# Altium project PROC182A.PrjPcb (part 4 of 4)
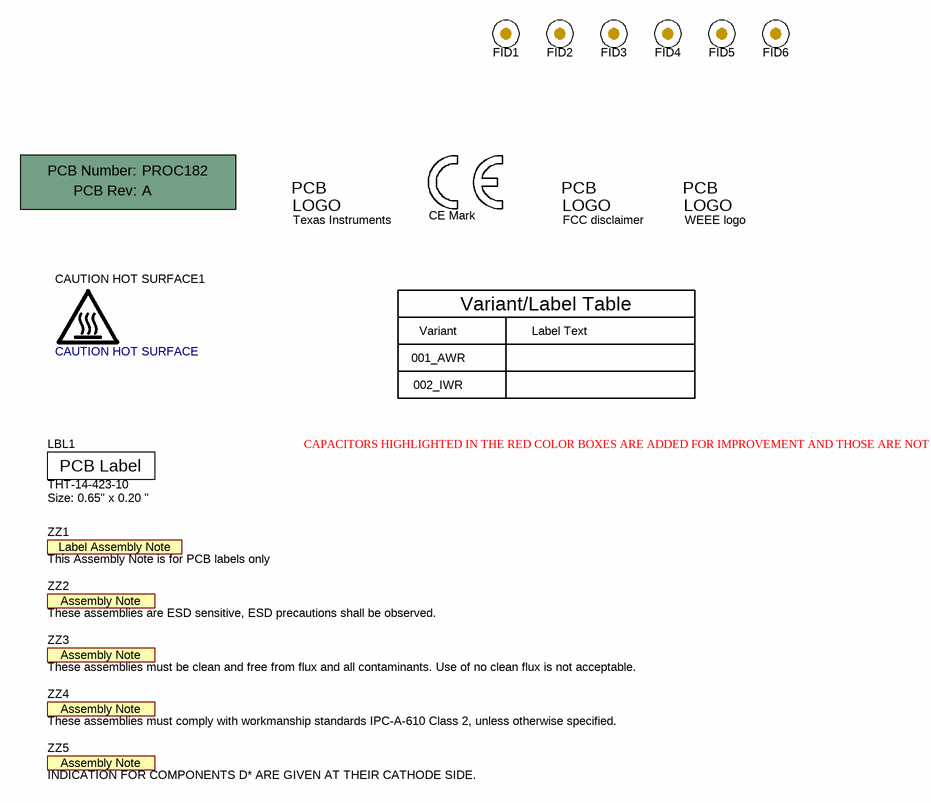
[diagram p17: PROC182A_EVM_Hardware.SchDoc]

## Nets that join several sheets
5V_IN_USB: PROC182A_USB_PWR_DC_Jack_Switch (15 pins), PROC182A_PMIC (C42.2 U13.6)
FTDI_VBUS: PROC182A_USB_PWR_DC_Jack_Switch (L8.1), PROC182A_FTDI (C157.2 J10.1 R259.2)
GND: PROC182A_USB_PWR_DC_Jack_Switch (45 pins), PROC182A_PMIC (46 pins), PROC182A_Chip (110 pins), PROC182A_Decoupling_caps- QSPI Flash (33 pins), PROC182A_Temp_Current_sensors_EPROM (24 pins), PROC182A_Analog_Mux_SOP_Ctrl (19 pins), PROC182A_Analog_MUX_SPI (9 pins), PROC182A_XDS110_Interface (33 pins), PROC182A_MUX_CAN_FD (8 pins), PROC182A_CAN_LIN_PHY_Interface (10 pins), PROC182A_FTDI (42 pins), PROC182A_DCA1000_Connector_Reset (25 pins), PROC182A_I2C_SPI_Connector (9 pins)
RADAR_1P2_RF: PROC182A_Chip (U1.D8 U1.D9 U1.D10), PROC182A_Decoupling_caps- QSPI Flash (C24.2 C44.1), PROC182A_Temp_Current_sensors_EPROM (R134.2 U25.9)
RADAR_1V2: PROC182A_Chip (25 pins), PROC182A_Decoupling_caps- QSPI Flash (8 pins), PROC182A_Temp_Current_sensors_EPROM (R193.2 U8.9)
RADAR_1V4_APLL: PROC182A_Chip (U1.H7), PROC182A_Decoupling_caps- QSPI Flash (C22.2)
RADAR_1V4_SYNTH: PROC182A_Chip (U1.F3), PROC182A_Decoupling_caps- QSPI Flash (C18.2)
RADAR_1V8: PROC182A_Chip (9 pins), PROC182A_Decoupling_caps- QSPI Flash (11 pins), PROC182A_Temp_Current_sensors_EPROM (R192.2 U6.9)
RADAR_1V_RF_OUT: PROC182A_Chip (5 pins), PROC182A_Decoupling_caps- QSPI Flash (C9.2 C19.2)
RADAR_3V3: PROC182A_Chip (10 pins), PROC182A_Decoupling_caps- QSPI Flash (C16.2 C17.2 C21.2), PROC182A_Temp_Current_sensors_EPROM (R200.2 U7.9)
RADAR_VBGAP: PROC182A_Chip (U1.K3), PROC182A_Decoupling_caps- QSPI Flash (C6.1)
REG_1V2: PROC182A_PMIC (C20.2 C91.2 FB2.2), PROC182A_Temp_Current_sensors_EPROM (R193.1 U8.8 U8.10)
REG_1V8: PROC182A_PMIC (C3.2 C82.2 FB1.2), PROC182A_Temp_Current_sensors_EPROM (R192.1 U6.8 U6.10)
REG_RF_1V2: PROC182A_PMIC (C27.2 C103.2 FB3.2), PROC182A_Temp_Current_sensors_EPROM (R134.1 U25.8 U25.10)
VCC_3V3: PROC182A_USB_PWR_DC_Jack_Switch (R172.2), PROC182A_PMIC (5 pins), PROC182A_Decoupling_caps- QSPI Flash (6 pins), PROC182A_Temp_Current_sensors_EPROM (33 pins), PROC182A_Analog_Mux_SOP_Ctrl (14 pins), PROC182A_Analog_MUX_SPI (11 pins), PROC182A_MUX_CAN_FD (8 pins), PROC182A_CAN_LIN_PHY_Interface (C38.2 R17.2 R22.2 U5.5), PROC182A_FTDI (R99.2), PROC182A_DCA1000_Connector_Reset (13 pins), PROC182A_I2C_SPI_Connector (8 pins)
VCC_CAN_3V3: PROC182A_PMIC (C72.2 L4.2), PROC182A_MUX_CAN_FD (R129.2), PROC182A_CAN_LIN_PHY_Interface (R69.2)
VCC_XDS_3V3: PROC182A_PMIC (C105.1 TP20.1 U13.1), PROC182A_XDS110_Interface (26 pins), PROC182A_FTDI (L7.1)
VPP_1P7: PROC182A_PMIC (P1.1), PROC182A_Chip (C31.1 U1.R4)
VSYS_IN: PROC182A_USB_PWR_DC_Jack_Switch (8 pins), PROC182A_PMIC (5 pins), PROC182A_CAN_LIN_PHY_Interface (J4.1 R31.1), PROC182A_DCA1000_Connector_Reset (R30.1), PROC182A_I2C_SPI_Connector (R155.2)
XDSET_1_VBUS: PROC182A_USB_PWR_DC_Jack_Switch (R1.1 U9.6), PROC182A_XDS110_Interface (R169.2 R236.2)
CAN_FD_B_PHY_RX: PROC182A_Chip (U1.U12), PROC182A_MUX_CAN_FD (R143.1)
CAN_FD_B_PHY_TX: PROC182A_Chip (U1.R11), PROC182A_MUX_CAN_FD (R132.1)
CAN_FD_B_STB_CTRL: PROC182A_Analog_Mux_SOP_Ctrl (S1.1), PROC182A_MUX_CAN_FD (R133.1)
CAN_FD_RX: PROC182A_MUX_CAN_FD (U18.5), PROC182A_CAN_LIN_PHY_Interface (R80.1)
CAN_FD_TX: PROC182A_MUX_CAN_FD (U18.9), PROC182A_CAN_LIN_PHY_Interface (R78.1)
CAN_FD_UARTA_RX: PROC182A_Chip (U1.R10), PROC182A_MUX_CAN_FD (U18.6)
CAN_FD_UARTA_TX: PROC182A_Chip (U1.T10), PROC182A_MUX_CAN_FD (U18.10)
CAN_STB_CTRL: PROC182A_Analog_Mux_SOP_Ctrl (S4.1), PROC182A_CAN_LIN_PHY_Interface (R3.1)
DCA_LP_FTDI_HOST_INTR_1: PROC182A_Chip (R81.2 R261.2 R276.1), PROC182A_Analog_MUX_SPI (U28.10)
DCA_LP_FTDI_SPIA_CLK: PROC182A_Chip (U1.A16), PROC182A_Analog_MUX_SPI (U28.4)
DCA_LP_FTDI_SPIA_CS: PROC182A_Chip (R246.1 U1.B17), PROC182A_Analog_MUX_SPI (U28.6)
DCA_LP_FTDI_SPIA_MISO: PROC182A_Chip (R284.1), PROC182A_Analog_MUX_SPI (U28.7)
DCA_LP_FTDI_SPIA_MOSI: PROC182A_Chip (U1.A15), PROC182A_Analog_MUX_SPI (U28.9)
DCA_LP_HOST_INTR_1: PROC182A_Analog_MUX_SPI (U28.19), PROC182A_DCA1000_Connector_Reset (R42.2), PROC182A_I2C_SPI_Connector (J2.2 R223.2)
DCA_LP_RS232_RX: PROC182A_Analog_Mux_SOP_Ctrl (U12.3), PROC182A_DCA1000_Connector_Reset (R61.1), PROC182A_I2C_SPI_Connector (R163.1 R178.1)
DCA_LP_RS232_TX: PROC182A_Analog_Mux_SOP_Ctrl (U12.15), PROC182A_DCA1000_Connector_Reset (R62.1), PROC182A_I2C_SPI_Connector (R156.1 R176.1)
DCA_LP_SPIA_CLK: PROC182A_Analog_MUX_SPI (U28.2), PROC182A_DCA1000_Connector_Reset (R41.1), PROC182A_I2C_SPI_Connector (J2.3 R210.1)
DCA_LP_SPIA_CS: PROC182A_Analog_MUX_SPI (U28.1), PROC182A_DCA1000_Connector_Reset (R39.1), PROC182A_I2C_SPI_Connector (J2.4 R173.1 R177.2)
DCA_LP_SPIA_MISO: PROC182A_Analog_MUX_SPI (U28.23), PROC182A_DCA1000_Connector_Reset (R53.2), PROC182A_I2C_SPI_Connector (J2.5 R221.2)
DCA_LP_SPIA_MOSI: PROC182A_Analog_MUX_SPI (U28.21), PROC182A_DCA1000_Connector_Reset (R52.1), PROC182A_I2C_SPI_Connector (J2.6 R201.2)
DCA_LP_UARTA_RX: PROC182A_Analog_Mux_SOP_Ctrl (U16.3), PROC182A_DCA1000_Connector_Reset (R152.2), PROC182A_I2C_SPI_Connector (J9.2 R198.1 R212.1)
DCA_LP_UARTA_TX: PROC182A_Analog_Mux_SOP_Ctrl (U16.1), PROC182A_DCA1000_Connector_Reset (R153.2), PROC182A_I2C_SPI_Connector (J9.1 R180.1 R182.1)
DCA_TCK: PROC182A_Analog_Mux_SOP_Ctrl (U4.16), PROC182A_DCA1000_Connector_Reset (R38.2)
DCA_TDI: PROC182A_Analog_Mux_SOP_Ctrl (U4.3), PROC182A_DCA1000_Connector_Reset (R37.1)
DCA_TDO: PROC182A_Analog_Mux_SOP_Ctrl (U4.9), PROC182A_DCA1000_Connector_Reset (R34.2)
DCA_TMS: PROC182A_Analog_Mux_SOP_Ctrl (U4.12), PROC182A_DCA1000_Connector_Reset (R40.2)
FTDI_DCA_LP_RS232_RX: PROC182A_Analog_Mux_SOP_Ctrl (U12.2), PROC182A_MUX_CAN_FD (U18.3)
FTDI_DCA_LP_RS232_TX: PROC182A_Analog_Mux_SOP_Ctrl (U12.14), PROC182A_MUX_CAN_FD (U18.15)
FTDI_HOST_INTR_1: PROC182A_Analog_MUX_SPI (U28.18), PROC182A_FTDI (R216.2 R217.2)
FTDI_RS232_RX: PROC182A_Analog_Mux_SOP_Ctrl (U12.1), PROC182A_FTDI (R120.2)
FTDI_RS232_TX: PROC182A_Analog_Mux_SOP_Ctrl (U12.13), PROC182A_FTDI (R121.2)
FTDI_SOP0: PROC182A_Analog_Mux_SOP_Ctrl (R13.1 R43.2 R235.1), PROC182A_FTDI (R249.2)
FTDI_SOP1: PROC182A_Analog_Mux_SOP_Ctrl (R16.1 R67.2 R244.1), PROC182A_FTDI (R248.2)
FTDI_SPI_CLK: PROC182A_Analog_MUX_SPI (U28.11), PROC182A_FTDI (R186.2)
FTDI_SPI_CS: PROC182A_Analog_MUX_SPI (U28.13), PROC182A_FTDI (R99.1 R209.2)
FTDI_SPI_MISO: PROC182A_Analog_MUX_SPI (U28.15), PROC182A_FTDI (R189.2)
FTDI_SPI_MOSI: PROC182A_Analog_MUX_SPI (U28.17), PROC182A_FTDI (R187.2)
FTDI_UARTA_RX: PROC182A_Analog_Mux_SOP_Ctrl (U16.4), PROC182A_FTDI (R118.2)
FTDI_UARTA_TX: PROC182A_Analog_Mux_SOP_Ctrl (U16.2), PROC182A_FTDI (R119.2)
HARDWARE_TRIGGER: PROC182A_Chip (J15.2), PROC182A_I2C_SPI_Connector (R254.1)
HOST_CLK_REQ_SPIB_MISO: PROC182A_Chip (R270.2), PROC182A_Analog_MUX_SPI (U30.7)
I2C_SCL: PROC182A_PMIC (R89.1), PROC182A_Temp_Current_sensors_EPROM (7 pins), PROC182A_Analog_MUX_SPI (U30.16), PROC182A_XDS110_Interface (R199.1 S5.2), PROC182A_FTDI (R96.2), PROC182A_DCA1000_Connector_Reset (R60.1), PROC182A_I2C_SPI_Connector (J1.1 R164.1 R224.1)
I2C_SCL_SPIB_CLK: PROC182A_Chip (U1.N16), PROC182A_Analog_MUX_SPI (U30.2)
I2C_SDA: PROC182A_PMIC (R90.1), PROC182A_Temp_Current_sensors_EPROM (7 pins), PROC182A_Analog_MUX_SPI (U30.3), PROC182A_XDS110_Interface (R197.1 S5.1), PROC182A_FTDI (R100.2 R102.2), PROC182A_DCA1000_Connector_Reset (R59.1), PROC182A_I2C_SPI_Connector (J1.2 R166.1 R238.1)
I2C_SDA_SPIB_MOSI: PROC182A_Chip (U1.N17), PROC182A_Analog_MUX_SPI (U30.5)
LIN_PHY_EN_CTRL: PROC182A_Analog_Mux_SOP_Ctrl (S4.2), PROC182A_CAN_LIN_PHY_Interface (R88.1)
LIN_PHY_RX: PROC182A_Analog_MUX_SPI (U24.1), PROC182A_CAN_LIN_PHY_Interface (R18.1 R22.1)
LIN_PHY_RX_UARTB_TX: PROC182A_Chip (U1.U13), PROC182A_Analog_MUX_SPI (U24.9)
LIN_PHY_TX: PROC182A_Analog_MUX_SPI (U24.3), PROC182A_CAN_LIN_PHY_Interface (R19.1)
LIN_PHY_TX_UARTB_RX: PROC182A_Chip (U1.T11), PROC182A_Analog_MUX_SPI (U24.6)
MCU_SOP0: PROC182A_Analog_Mux_SOP_Ctrl (R235.2), PROC182A_I2C_SPI_Connector (J12.19)
MCU_SOP1: PROC182A_Analog_Mux_SOP_Ctrl (R244.2), PROC182A_I2C_SPI_Connector (J12.17)
MUX_CTRL_FTDI_DCA_SPIA: PROC182A_Analog_Mux_SOP_Ctrl (S4.3), PROC182A_Analog_MUX_SPI (R12.2 U28.14 U28.24)
MUX_CTRL_LIN_UARTB: PROC182A_Analog_Mux_SOP_Ctrl (S4.5), PROC182A_Analog_MUX_SPI (R253.1 U24.7 U24.8)
MUX_CTRL_SPIB_I2C_SYS_RST_HOST_CLK_REQ: PROC182A_Analog_Mux_SOP_Ctrl (S4.6), PROC182A_Analog_MUX_SPI (R271.1 U30.15)
MUX_CTRL_UARTA_CAN_FD: PROC182A_Analog_Mux_SOP_Ctrl (S1.4), PROC182A_MUX_CAN_FD (R128.1 U18.8)
MUX_CTRL_XDS_FTDI_DCA_LP_RS232: PROC182A_Analog_Mux_SOP_Ctrl (S1.2), PROC182A_MUX_CAN_FD (R127.1 U18.16)
PGOOD: PROC182A_USB_PWR_DC_Jack_Switch (R179.1), PROC182A_PMIC (R91.1 R92.2 R241.1), PROC182A_DCA1000_Connector_Reset (R58.1), PROC182A_I2C_SPI_Connector (R211.2)
PMIC_CAN_STB_CTRL: PROC182A_PMIC (R85.1), PROC182A_MUX_CAN_FD (R131.1), PROC182A_CAN_LIN_PHY_Interface (R273.1)
PMIC_CLKOUT_SOP1: PROC182A_Chip (U1.C17), PROC182A_Analog_Mux_SOP_Ctrl (R15.1 R206.1), PROC182A_I2C_SPI_Connector (R240.2)
PMIC_RADAR_nINT: PROC182A_PMIC (R245.1), PROC182A_Chip (R257.1 U1.P16)
QSPI_CS: PROC182A_Chip (U1.A13), PROC182A_Decoupling_caps- QSPI Flash (R50.2 U2.1)
QSPI_D0: PROC182A_Chip (U1.A12), PROC182A_Decoupling_caps- QSPI Flash (R45.2)
QSPI_D1: PROC182A_Chip (U1.B13), PROC182A_Decoupling_caps- QSPI Flash (R46.1)
QSPI_D2: PROC182A_Chip (U1.B12), PROC182A_Decoupling_caps- QSPI Flash (R44.1 R47.1)
QSPI_D3: PROC182A_Chip (U1.B11), PROC182A_Decoupling_caps- QSPI Flash (R49.1 R51.2)
QSPI_SCLK: PROC182A_Chip (U1.B14), PROC182A_Decoupling_caps- QSPI Flash (R48.2)
RADAR_LVDS_0M: PROC182A_Chip (U1.G17), PROC182A_DCA1000_Connector_Reset (R230.2)
RADAR_LVDS_0P: PROC182A_Chip (U1.G16), PROC182A_DCA1000_Connector_Reset (R229.2)
RADAR_LVDS_1M: PROC182A_Chip (U1.M17), PROC182A_DCA1000_Connector_Reset (R228.2)
RADAR_LVDS_1P: PROC182A_Chip (U1.M16), PROC182A_DCA1000_Connector_Reset (R227.2)
RADAR_LVDS_CLKM: PROC182A_Chip (U1.J17), PROC182A_DCA1000_Connector_Reset (R226.2)
RADAR_LVDS_CLKP: PROC182A_Chip (U1.H16), PROC182A_DCA1000_Connector_Reset (R225.2)
RADAR_LVDS_FRCLKM: PROC182A_Chip (U1.K17), PROC182A_DCA1000_Connector_Reset (R220.2)
RADAR_LVDS_FRCLKP: PROC182A_Chip (U1.L16), PROC182A_DCA1000_Connector_Reset (R219.2)
RADAR_nERROR_OUT: PROC182A_PMIC (R288.1 R289.2 U15.13), PROC182A_Chip (R247.1 U1.N15), PROC182A_DCA1000_Connector_Reset (D13.1)
RADAR_NRST: PROC182A_Chip (C134.2 R250.1 U1.U10), PROC182A_DCA1000_Connector_Reset (R171.2 U17.4)
RADAR_NRST_1: PROC182A_PMIC (D4.2), PROC182A_DCA1000_Connector_Reset (R63.1 R123.1 U17.1), PROC182A_I2C_SPI_Connector (R183.2)
RADAR_NRST_2: PROC182A_FTDI (R243.2), PROC182A_DCA1000_Connector_Reset (5 pins)
RADAR_USER_LED_GPIO_6: PROC182A_Chip (R269.2 U1.U15), PROC182A_FTDI (R242.2), PROC182A_DCA1000_Connector_Reset (R263.2 R264.2), PROC182A_I2C_SPI_Connector (R222.1)
RADAR_USER_SW_GPIO_2: PROC182A_Chip (U1.F16), PROC182A_DCA1000_Connector_Reset (R66.2 R214.2), PROC182A_I2C_SPI_Connector (R175.1)
SPIB_CLK: PROC182A_Analog_MUX_SPI (U30.1), PROC182A_I2C_SPI_Connector (R285.2)
SPIB_CS0_N: PROC182A_Analog_MUX_SPI (U30.11), PROC182A_I2C_SPI_Connector (J14.4)
SPIB_MISO: PROC182A_Analog_MUX_SPI (U30.8), PROC182A_I2C_SPI_Connector (J14.5)
SPIB_MOSI: PROC182A_Analog_MUX_SPI (U30.4), PROC182A_I2C_SPI_Connector (R286.2)
SYS_RST_OUT: PROC182A_Analog_MUX_SPI (U30.12), PROC182A_DCA1000_Connector_Reset (D9.1 R65.2)
SYS_RST_OUT_SPIB_CS0_N: PROC182A_Chip (R146.1 R268.2), PROC182A_Analog_MUX_SPI (U30.10)
UARTB_RX: PROC182A_Analog_MUX_SPI (R275.1 U24.4), PROC182A_I2C_SPI_Connector (J13.2)
UARTB_TX: PROC182A_Analog_MUX_SPI (R274.1 U24.2), PROC182A_I2C_SPI_Connector (J13.1)
XDS_DCA_LP_FTDI_UARTA_RX: PROC182A_Analog_Mux_SOP_Ctrl (U12.6), PROC182A_MUX_CAN_FD (R147.2 U18.7)
XDS_DCA_LP_FTDI_UARTA_TX: PROC182A_Analog_Mux_SOP_Ctrl (U12.10), PROC182A_MUX_CAN_FD (R149.2 U18.11)
XDS_DCA_TCK: PROC182A_Chip (U1.T12), PROC182A_Analog_Mux_SOP_Ctrl (U4.2)
XDS_DCA_TDI: PROC182A_Chip (U1.T14), PROC182A_Analog_Mux_SOP_Ctrl (U4.5)
XDS_DCA_TDO_SOP0: PROC182A_Chip (R93.1), PROC182A_Analog_Mux_SOP_Ctrl (R203.1 U4.7)
XDS_DCA_TMS: PROC182A_Chip (U1.T15), PROC182A_Analog_Mux_SOP_Ctrl (U4.10)
XDS_FTDI_DCA_RS232_RX: PROC182A_Chip (R255.1 U1.R14), PROC182A_MUX_CAN_FD (U18.2)
XDS_FTDI_DCA_RS232_TX: PROC182A_Chip (R256.1 U1.P15), PROC182A_MUX_CAN_FD (U18.14)
XDS_NRST: PROC182A_XDS110_Interface (R126.2), PROC182A_DCA1000_Connector_Reset (R138.1 U17.3)
XDS_RS232_RX: PROC182A_XDS110_Interface (R24.2 R188.1), PROC182A_MUX_CAN_FD (U18.1)
XDS_RS232_TX: PROC182A_XDS110_Interface (R26.2 R181.1), PROC182A_MUX_CAN_FD (U18.13)
XDS_SOP0: PROC182A_Analog_Mux_SOP_Ctrl (R43.1), PROC182A_XDS110_Interface (U21.42)
XDS_SOP1: PROC182A_Analog_Mux_SOP_Ctrl (R67.1), PROC182A_XDS110_Interface (U21.43)
XDS_TCK: PROC182A_Analog_Mux_SOP_Ctrl (U4.1), PROC182A_XDS110_Interface (R122.2)
XDS_TDI: PROC182A_Analog_Mux_SOP_Ctrl (U4.4), PROC182A_XDS110_Interface (R125.2)
XDS_TDO: PROC182A_Analog_Mux_SOP_Ctrl (U4.8), PROC182A_XDS110_Interface (U21.37), PROC182A_I2C_SPI_Connector (R232.2)
XDS_TMS: PROC182A_Analog_Mux_SOP_Ctrl (U4.11), PROC182A_XDS110_Interface (R124.2)
XDS_UARTA_RX: PROC182A_Analog_Mux_SOP_Ctrl (U12.7), PROC182A_XDS110_Interface (R24.1 R290.1)
XDS_UARTA_TX: PROC182A_Analog_Mux_SOP_Ctrl (U12.11), PROC182A_XDS110_Interface (R26.1 R190.1)
XDSET_1_DM: PROC182A_USB_PWR_DC_Jack_Switch (J5.2 U9.4), PROC182A_XDS110_Interface (U21.93)
XDSET_1_DP: PROC182A_USB_PWR_DC_Jack_Switch (J5.3 U9.5), PROC182A_XDS110_Interface (U21.94)
XDSET_1_ID: PROC182A_USB_PWR_DC_Jack_Switch (J5.4 U9.2), PROC182A_XDS110_Interface (R170.2)

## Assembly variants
01_AWR: not fitted C70 C71 C80 C81 C89 C90 FID1 FID2 FID3 FID4 FID5 FID6 J9 J11 J12 J13 J14 R2 R14 R15 R24 R26 R30 R32 R54 R59 R60 R65 R73 R76 R82 R83 R84 R85 R92 R96 R100 R102 R107 R113 R114 R116 R131 R135 R150 R152 R153 R154 R155 R156 R157 R161 R163 R164 R166 R173 R180 R197 R198 R199 R235 R242 R244 R247 R248 R249 R254 R273 R276 R278 R279
02_IWR: not fitted C70 C71 C80 C81 C89 C90 FID1 FID2 FID3 FID4 FID5 FID6 J4 J9 J11 J12 J13 J14 R2 R14 R15 R24 R26 R30 R32 R54 R59 R60 R65 R73 R76 R82 R83 R84 R85 R92 R96 R100 R102 R107 R113 R114 R116 R131 R135 R150 R152 R153 R154 R155 R156 R157 R161 R163 R164 R166 R173 R180 R197 R198 R199 R235 R242 R244 R247 R248 R249 R254 R273 R276 R278 R279 U23; alternate parts U1 -> CMP-0124118-1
